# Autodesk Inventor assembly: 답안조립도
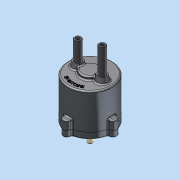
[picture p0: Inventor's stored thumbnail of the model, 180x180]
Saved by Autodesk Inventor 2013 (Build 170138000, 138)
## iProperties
Created: 2015-02
Part Number: 답안조립도
Document SubType Name: Assembly
Designer: dgall
Mass: 1967.31 g
Surface Area: 1692.74 cm^2
Volume: 412.889 cm^3
Density: 4.76474 g/cm^3
Author: dgall
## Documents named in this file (13)
- C:\Documents and Settings\dgall\바탕 화면\350207V1028\답안조립도.iam
- C:\Documents and Settings\dgall\바탕 화면\350207V1028\몸체.ipt
- C:\Documents and Settings\dgall\바탕 화면\350207V1028\메인 축.ipt
- C:\Documents and Settings\dgall\바탕 화면\350207V1028\판캠.ipt
- C:\Documents and Settings\dgall\바탕 화면\350207V1028\멈춤링 22 x 1.2.ipt
- C:\Documents and Settings\dgall\바탕 화면\350207V1028\멈춤링 10 x 1.ipt
- C:\Documents and Settings\dgall\바탕 화면\350207V1028\베어링 NA 4900.ipt
- C:\Documents and Settings\dgall\바탕 화면\350207V1028\슬라이드 축.ipt
- C:\Documents and Settings\dgall\바탕 화면\350207V1028\가변 스프링 11.ipt
- C:\Documents and Settings\dgall\바탕 화면\350207V1028\가변 스프링 12.ipt
- C:\Documents and Settings\dgall\바탕 화면\350207V1028\커버.ipt
- C:\Documents and Settings\dgall\바탕 화면\350207V1028\오일실.ipt
- C:\Documents and Settings\dgall\바탕 화면\350207V1028\M5x0.5x20.ipt
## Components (6 placed, 3 different names)
1. 가변 스프링 11:1
2. 가변 스프링 12:1
3. M5x0.5x20:1
4. M5x0.5x20:2
5. M5x0.5x20:3
6. M5x0.5x20:4
